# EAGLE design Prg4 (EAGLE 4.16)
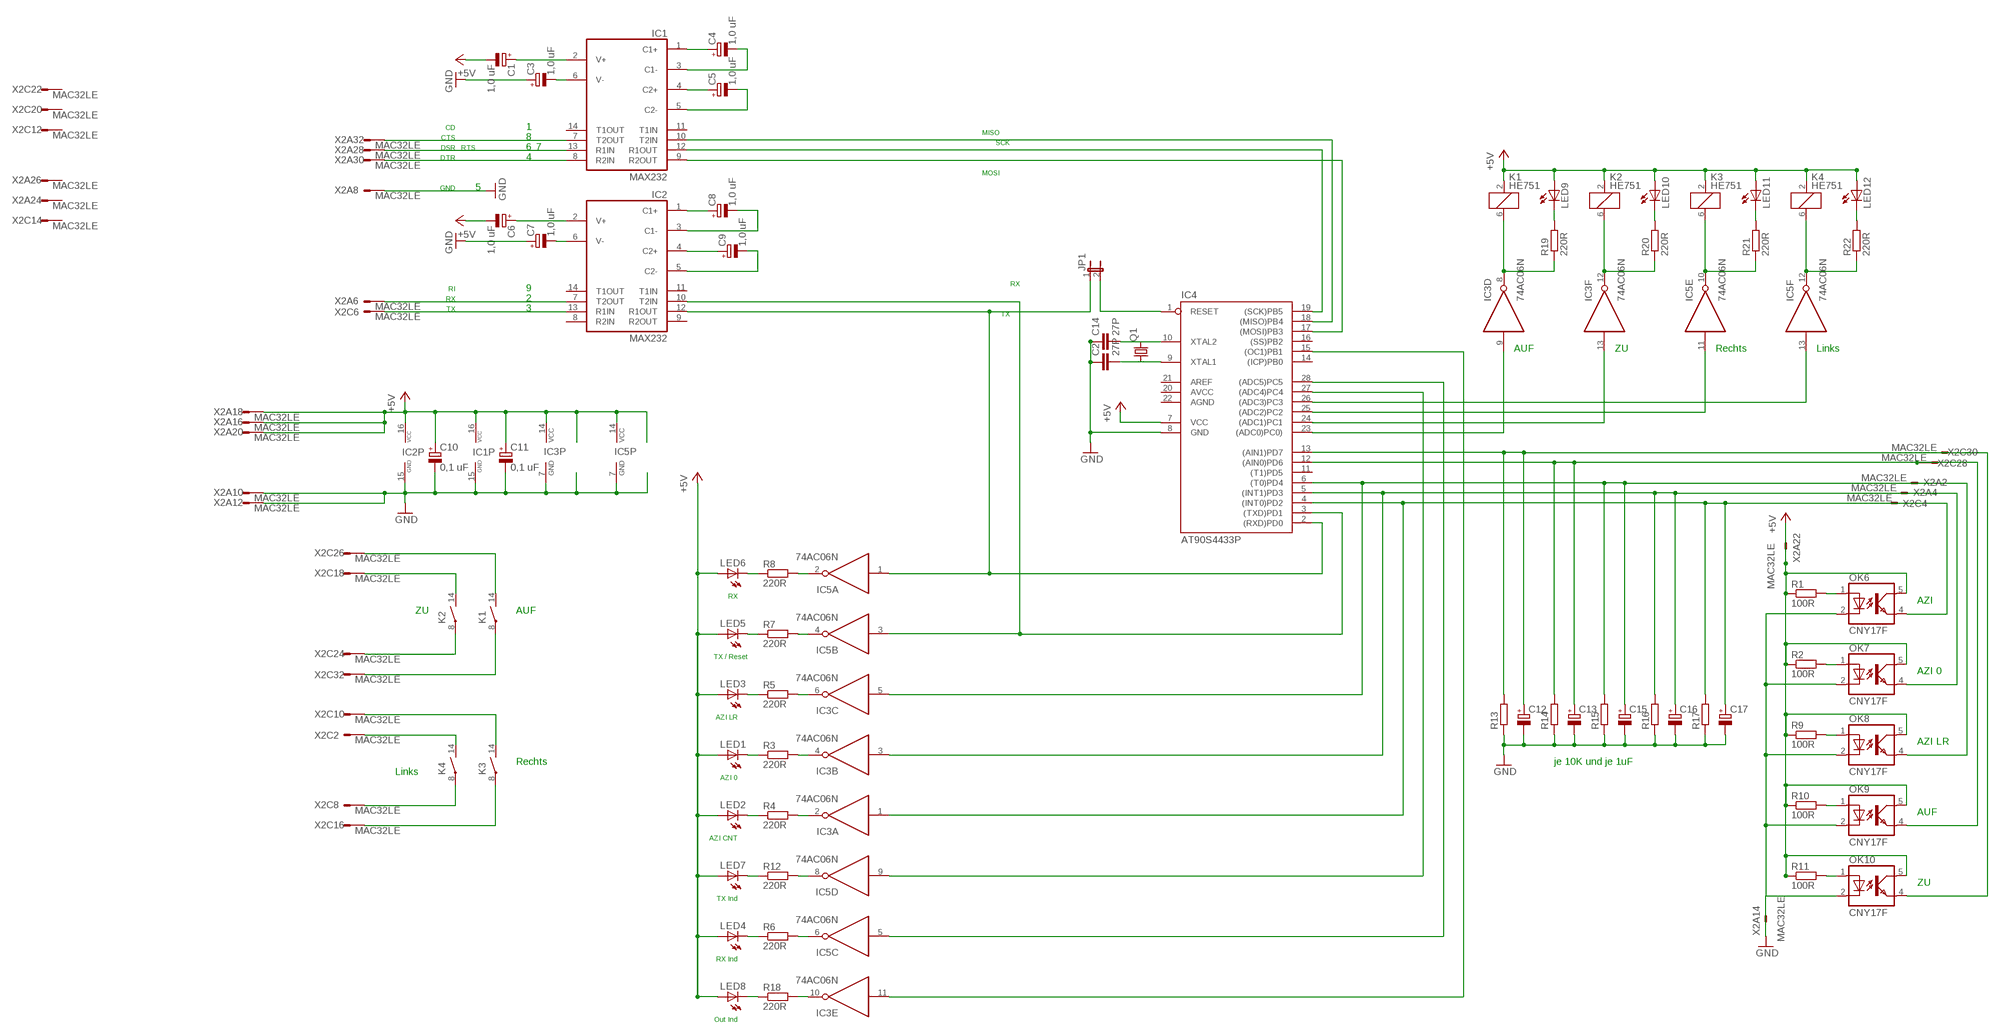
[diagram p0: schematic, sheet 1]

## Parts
C1  1,0 uF  CPOL-EUE2,5-6E  [E2,5-6E]
C2  27P  C-EU025-024X044  [C025-024X044]
C3  1,0 uF  CPOL-EUE2,5-6E  [E2,5-6E]
C4  1,0 uF  CPOL-EUE2,5-6E  [E2,5-6E]
C5  1,0 uF  CPOL-EUE2,5-6E  [E2,5-6E]
C6  1,0 uF  CPOL-EUE2,5-6E  [E2,5-6E]
C7  1,0 uF  CPOL-EUE2,5-6E  [E2,5-6E]
C8  1,0 uF  CPOL-EUE2,5-6E  [E2,5-6E]
C9  1,0 uF  CPOL-EUE2,5-6E  [E2,5-6E]
C10  0,1 uF  CPOL-EUE2,5-6E  [E2,5-6E]
C11  0,1 uF  CPOL-EUE2,5-6E  [E2,5-6E]
C12  CPOL-EUE2.5-4V  [E2,5RE]
C13  CPOL-EUE2.5-4V  [E2,5RE]
C14  27P  C-EU025-024X044  [C025-024X044]
C15  CPOL-EUE2.5-4V  [E2,5RE]
C16  CPOL-EUE2.5-4V  [E2,5RE]
C17  CPOL-EUE2.5-4V  [E2,5RE]
IC1  MAX232  [DIL16]
IC2  MAX232  [DIL16]
IC3  74AC06N  [DIL14]
IC4  AT90S4433P  [DIL28-3]
IC5  74AC06N  [DIL14]
JP1  JP1E  [JP1]
K1  HE751  [HE751]
K2  HE751  [HE751]
K3  HE751  [HE751]
K4  HE751  [HE751]
LED1  LED3MM  [LED3MM]
LED2  LED3MM  [LED3MM]
LED3  LED3MM  [LED3MM]
LED4  LED3MM  [LED3MM]
LED5  LED3MM  [LED3MM]
LED6  LED3MM  [LED3MM]
LED7  LED3MM  [LED3MM]
LED8  LED3MM  [LED3MM]
LED9  LED3MM  [LED3MM]
LED10  LED3MM  [LED3MM]
LED11  LED3MM  [LED3MM]
LED12  LED3MM  [LED3MM]
OK6  CNY17F  [DIL06]
OK7  CNY17F  [DIL06]
OK8  CNY17F  [DIL06]
OK9  CNY17F  [DIL06]
OK10  CNY17F  [DIL06]
Q1  CRYTALHC49S  [HC49/S]
R1  100R  R-EU_0204/7  [0204/7]
R2  100R  R-EU_0204/7  [0204/7]
R3  220R  R-EU_0207/2V  [0207/2V]
R4  220R  R-EU_0207/2V  [0207/2V]
R5  220R  R-EU_0207/2V  [0207/2V]
R6  220R  R-EU_0207/2V  [0207/2V]
R7  220R  R-EU_0207/2V  [0207/2V]
R8  220R  R-EU_0207/2V  [0207/2V]
R9  100R  R-EU_0204/7  [0204/7]
R10  100R  R-EU_0204/7  [0204/7]
R11  100R  R-EU_0204/7  [0204/7]
R12  220R  R-EU_0207/2V  [0207/2V]
R13  R-EU_0204/5  [0204/5]
R14  R-EU_0204/2V  [0204V]
R15  R-EU_0204/2V  [0204V]
R16  R-EU_0204V/3  [0204V/3]
R17  R-EU_0204/5  [0204/5]
R18  220R  R-EU_0207/2V  [0207/2V]
R19  220R  R-EU_0204V/3  [0204V/3]
R20  220R  R-EU_0207/2V  [0207/2V]
R21  220R  R-EU_0207/2V  [0207/2V]
R22  220R  R-EU_0207/2V  [0207/2V]
X2  MAC32LE  [MAC32L]

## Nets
+5V: C1.- C6.- C10.+ C11.+ IC1.16(VCC) IC2.16(VCC) IC3.14(P:VCC) IC4.7(VCC) IC5.14(P:VCC) K1.2 K2.2 K3.2 K4.2 LED1.A LED2.A LED3.A LED4.A LED5.A LED6.A LED7.A LED8.A LED9.A LED10.A LED11.A LED12.A OK6.5(COL) OK7.5(COL) OK8.5(COL) OK9.5(COL) OK10.5(COL) R1.1 R2.1 R9.1 R10.1 R11.1 X2.A16 X2.A18 X2.A20 X2.A22
GND: C2.1 C3.+ C7.+ C10.- C11.- C12.- C13.- C14.1 C15.- C16.- C17.- IC1.15(GND) IC2.15(GND) IC3.7(P:GND) IC4.8(GND) IC5.7(P:GND) OK6.2(C) OK7.2(C) OK8.2(C) OK9.2(C) OK10.2(C) R13.1 R14.1 R15.1 R16.1 R17.1 X2.A8 X2.A10 X2.A12 X2.A14
N$1: C4.+ IC1.1(C1+)
N$2: C4.- IC1.3(C1-)
N$3: C5.+ IC1.4(C2+)
N$4: C5.- IC1.5(C2-)
N$5: C3.- IC1.6(V-)
N$6: C1.+ IC1.2(V+)
N$7: C6.+ IC2.2(V+)
N$8: C7.- IC2.6(V-)
N$9: C8.+ IC2.1(C1+)
N$10: C9.+ IC2.4(C2+)
N$11: C9.- IC2.5(C2-)
N$12: C8.- IC2.3(C1-)
N$13: K2.14(2:S) X2.C18
N$14: K4.8(2:P) X2.C8
N$15: K3.14(2:S) X2.C10
N$16: K4.14(2:S) X2.C2
N$17: IC1.13(R1IN) X2.A28
N$18: IC1.8(R2IN) X2.A30
N$19: IC2.7(T2OUT) X2.A6
N$20: IC1.9(R2OUT) IC4.17((MOSI)PB3)
N$21: IC3.8(D:O) K1.6 R19.1
N$22: IC3.12(F:O) K2.6 R20.1
N$23: IC2.12(R1OUT) IC4.2((RXD)PD0) IC5.1(A:I) JP1.1
N$24: IC2.10(T2IN) IC4.3((TXD)PD1) IC5.3(B:I)
N$25: LED1.K(C) R3.1
N$26: IC3.4(B:O) R3.2
N$27: LED2.K(C) R4.1
N$28: IC3.2(A:O) R4.2
N$29: LED3.K(C) R5.1
N$30: IC3.6(C:O) R5.2
N$31: LED4.K(C) R6.1
N$32: IC5.6(C:O) R6.2
N$33: LED5.K(C) R7.1
N$34: IC5.4(B:O) R7.2
N$35: C14.2 IC4.10(XTAL2) Q1.2
N$36: C2.2 IC4.9(XTAL1) Q1.1
N$37: IC3.9(D:I) IC4.23((ADC0)PC0))
N$38: IC5.12(F:O) K4.6 R22.1
N$39: IC4.26((ADC3)PC3) IC5.13(F:I)
N$40: IC5.10(E:O) K3.6 R21.1
N$41: IC1.10(T2IN) IC4.18((MISO)PB4)
N$42: IC4.1(RESET) JP1.2
N$43: IC5.2(A:O) R8.2
N$44: IC5.8(D:O) R12.2
N$45: LED6.K(C) R8.1
N$46: LED7.K(C) R12.1
N$47: IC4.27((ADC4)PC4) IC5.9(D:I)
N$48: IC4.28((ADC5)PC5) IC5.5(C:I)
N$49: IC1.12(R1OUT) IC4.19((SCK)PB5)
N$50: IC3.13(F:I) IC4.24((ADC1)PC1)
N$51: IC4.25((ADC2)PC2) IC5.11(E:I)
N$52: OK6.1(A) R1.2
N$53: OK7.1(A) R2.2
N$54: OK8.1(A) R9.2
N$55: OK9.1(A) R10.2
N$56: OK10.1(A) R11.2
N$57: IC1.7(T2OUT) X2.A32
N$58: C16.+ IC3.3(B:I) IC4.5((INT1)PD3) OK7.4(EMIT) R16.2 X2.A4
N$59: IC3.10(E:O) R18.2
N$60: C15.+ IC3.5(C:I) IC4.6((T0)PD4) OK8.4(EMIT) R15.2 X2.A2
N$61: C13.+ IC4.12((AIN0)PD6) OK9.4(EMIT) R14.2 X2.C28
N$62: K1.14(2:S) X2.C26
N$63: C12.+ IC4.13((AIN1)PD7) OK10.4(EMIT) R13.2 X2.C30
N$64: K2.8(2:P) X2.C24
N$65: C17.+ IC3.1(A:I) IC4.4((INT0)PD2) OK6.4(EMIT) R17.2 X2.C4
N$66: IC2.13(R1IN) X2.C6
N$67: LED8.K(C) R18.1
N$68: IC3.11(E:I) IC4.15((OC1)PB1)
N$69: LED9.K(C) R19.2
N$70: LED10.K(C) R20.2
N$71: K1.8(2:P) X2.C32
N$72: K3.8(2:P) X2.C16
N$73: LED11.K(C) R21.2
N$74: LED12.K(C) R22.2
Unconnected: IC1.11(T1IN) IC1.14(T1OUT) IC2.8(R2IN) IC2.9(R2OUT) IC2.11(T1IN) IC2.14(T1OUT) IC4.11((T1)PD5) IC4.14((ICP)PB0) IC4.16((SS)PB2) X2.A24 X2.A26 X2.C12 X2.C14 X2.C20 X2.C22

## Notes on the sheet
- CD | 1 | MISO
- CTS | 8 | SCK
- DSR | RTS | 6 | 7
- DTR | 4
- MOSI
- GND | 5
- RX
- RI | 9
- RX | 2
- TX | 3 | TX
- AUF | ZU | Rechts | Links
- RX
- AZI
- ZU | AUF
- TX / Reset
- AZI 0
- AZI LR
- AZI LR
- Rechts | je 10K und je 1uF
- Links | AZI 0
- AUF
- AZI CNT
- ZU
- TX Ind
- RX Ind
- Out Ind

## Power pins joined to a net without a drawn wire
AGND: IC4.22(AGND)
AREF: IC4.21(AREF)
AVCC: IC4.20(AVCC)

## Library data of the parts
C1 C3-C13 C15-C17 = rcl:CPOL-EU: POLARIZED CAPACITOR, European symbol
C2 C14 = rcl:C-EU: CAPACITOR, European symbol
IC1 IC2 = maxim:MAX232: RS232 TRANSEIVER
IC3 IC5 = 74xx-eu:74*06: Hex INVERTER, open collector high-voltage output
IC4 = atmel:AT90S4433: MICROCONTROLLER 4 Kbytes FLASH 128 bytes SRAM 256 bytes EEPROM UART 6-channel 10 bit ADC
JP1 = jumper:JP1E: JUMPER
K1-K4 = relay:HE751: RELAY reed, 1 x norm. open, Hamlin
LED1-LED12 = led:LED: LED
OK6-OK10 = optocoupler:CNY17F: SIEMENS OPTO COUPLER
Q1 = crystal:CRYTAL: CRYSTAL
R1-R22 = rcl:R-EU_: RESISTOR, European symbol
X2 = con-vg:MAC32LE: CONNECTOR male, 32 pins, single, type D, rows AC, grid 5.08 mm with mounting clip

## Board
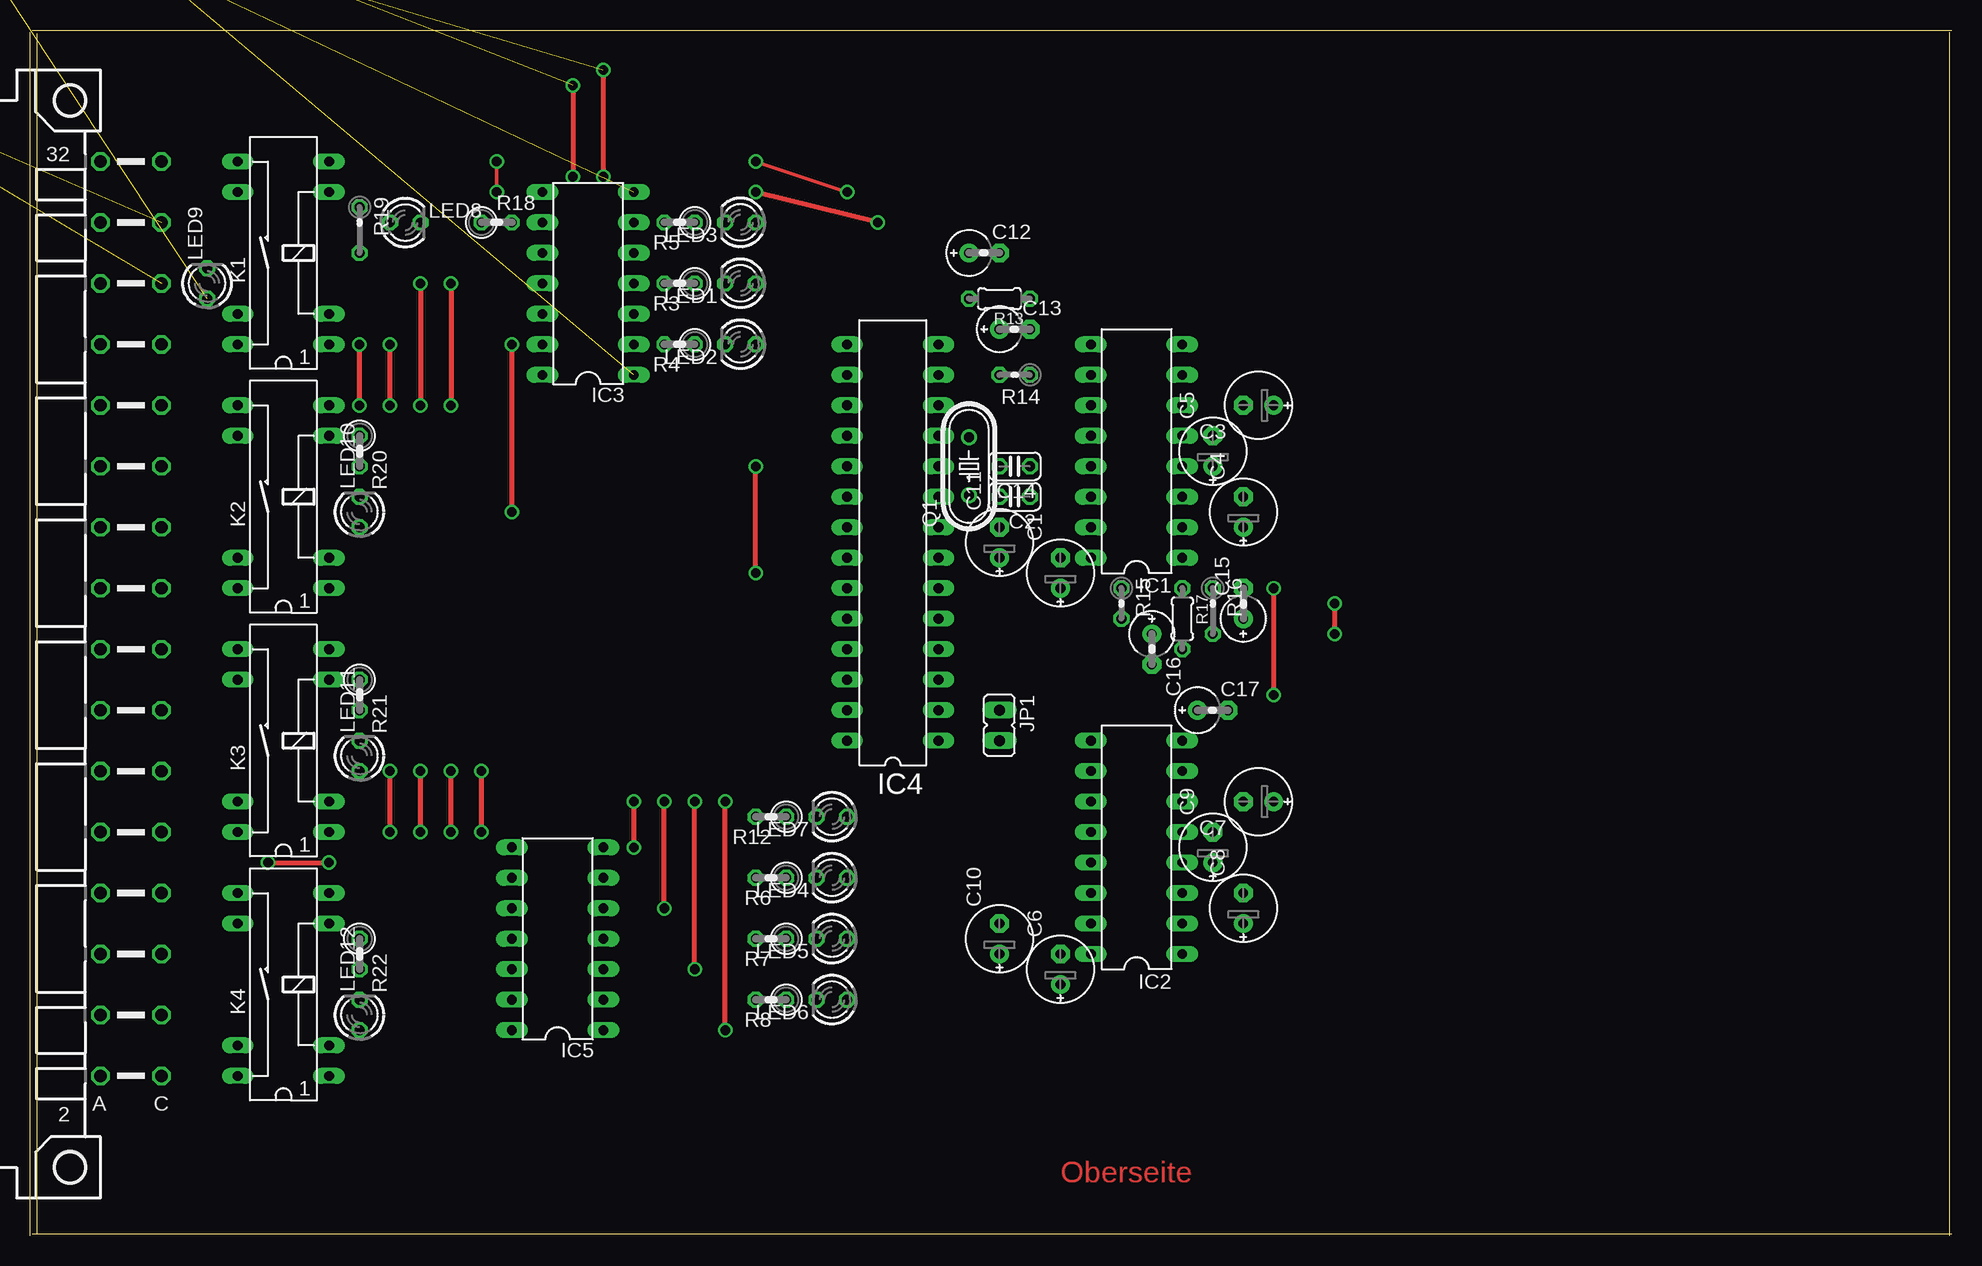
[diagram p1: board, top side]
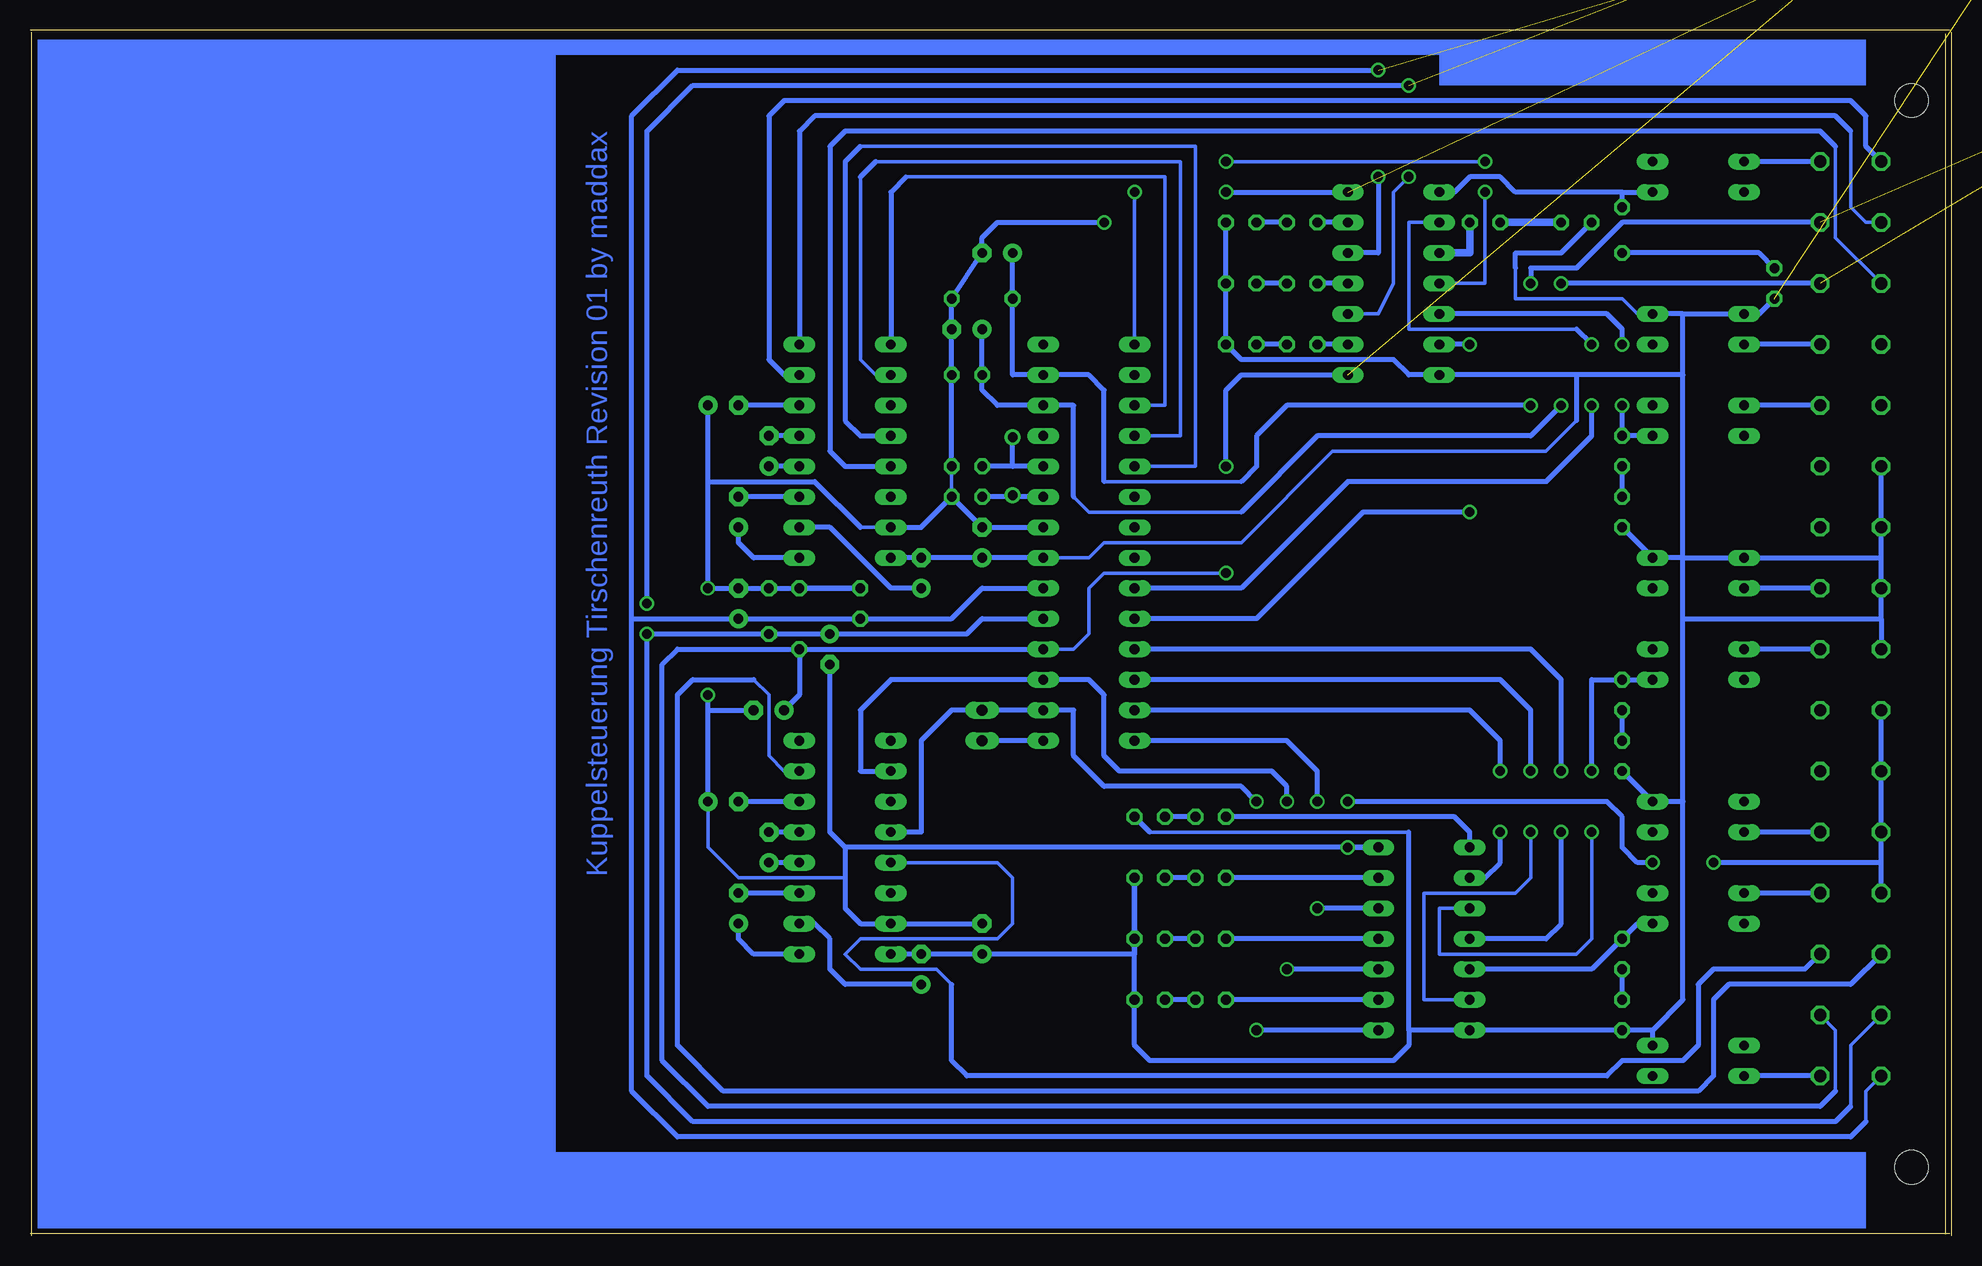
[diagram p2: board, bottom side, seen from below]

Size 160.18 x 100.49 mm. Coordinates in mm from the lower left corner, seen from the top.
Outline: 160.02,0 160.02,100.32
Outline: 80.18,100.49 160.18,100.49
Outline: 0.17,100.49 80.17,100.49
Outline: 0,0 0,100.32
Outline: 0.17,0.16 80.17,0.16
Outline: 80.18,0.16 160.18,0.16
Copper layers (1*16): Top 0.035mm / dielectric 1.5mm / Bottom 0.035mm
Design rules "default": minimum track width 10mil, minimum drill 24mil, track to track 8mil, track to pad 8mil, pad to pad 8mil, via to via 8mil, smd to smd 8mil, copper to edge 40mil, drill to drill 8mil, minimum pad ring 10mil, minimum via ring 8mil, stop-mask expansion 4mil, vias tented up to drill 0mil, thermal gap 10mil

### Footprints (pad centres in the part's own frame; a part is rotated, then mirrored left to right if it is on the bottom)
E2,5-6E = drill 0.813 pad 1.575 round: + -1.27,0 | drill 0.813 pad 1.575 octagon: - 1.27,0
C025-024X044 = drill 0.813 octagon: 1 -1.27,0; 2 1.27,0
E2,5RE = drill 0.813 pad 1.575 round: + -1.27,0 | drill 0.813 pad 1.575 octagon: - 1.27,0
DIL16 = drill 0.813 long: 1 -8.89,-3.81; 2 -6.35,-3.81; 3 -3.81,-3.81; 4 -1.27,-3.81; 5 1.27,-3.81; 6 3.81,-3.81; 7 6.35,-3.81; 8 8.89,-3.81; 9 8.89,3.81; 10 6.35,3.81; 11 3.81,3.81; 12 1.27,3.81; 13 -1.27,3.81; 14 -3.81,3.81; 15 -6.35,3.81; 16 -8.89,3.81
DIL14 = drill 0.813 long: 1 -7.62,-3.81; 2 -5.08,-3.81; 3 -2.54,-3.81; 4 0,-3.81; 5 2.54,-3.81; 6 5.08,-3.81; 7 7.62,-3.81; 8 7.62,3.81; 9 5.08,3.81; 10 2.54,3.81; 11 0,3.81; 12 -2.54,3.81; 13 -5.08,3.81; 14 -7.62,3.81
DIL28-3 = drill 0.813 long: 1 -16.51,-3.81; 2 -13.97,-3.81; 3 -11.43,-3.81; 4 -8.89,-3.81; 5 -6.35,-3.81; 6 -3.81,-3.81; 7 -1.27,-3.81; 8 1.27,-3.81; 9 3.81,-3.81; 10 6.35,-3.81; 11 8.89,-3.81; 12 11.43,-3.81; 13 13.97,-3.81; 14 16.51,-3.81; 15 16.51,3.81; 16 13.97,3.81; 17 11.43,3.81; 18 8.89,3.81; 19 6.35,3.81; 20 3.81,3.81; 21 1.27,3.81; 22 -1.27,3.81; 23 -3.81,3.81; 24 -6.35,3.81; 25 -8.89,3.81; 26 -11.43,3.81; 27 -13.97,3.81; 28 -16.51,3.81
JP1 = drill 0.914 long: 1 0,-1.27; 2 0,1.27
HE751 = drill 0.813 long: 1 -7.62,-3.81; 2 -5.08,-3.81; 6 5.08,-3.81; 7 7.62,-3.81; 8 7.62,3.81; 9 5.08,3.81; 13 -5.08,3.81; 14 -7.62,3.81
LED3MM = drill 0.813 octagon: A -1.27,0; K 1.27,0
DIL06 = drill 0.813 long: 1 -2.54,-3.81; 2 0,-3.81; 3 2.54,-3.81; 4 2.54,3.81; 5 0,3.81; 6 -2.54,3.81
HC49/S = drill 0.813 round: 1 -2.413,0; 2 2.413,0
0204/7 = drill 0.813 octagon: 1 -3.81,0; 2 3.81,0
0207/2V = drill 0.813 octagon: 1 -1.27,0; 2 1.27,0
0204/5 = drill 0.813 octagon: 1 -2.54,0; 2 2.54,0
0204V = drill 0.813 octagon: 1 -1.27,0; 2 1.27,0
0204V/3 = drill 0.813 octagon: 1 -1.27,0; 2 2.54,0
MAC32L = drill 1.016 octagon: A2 -2.54,36.83; A4 -2.54,31.75; A6 -2.54,26.67; A8 -2.54,21.59; A10 -2.54,16.51; A12 -2.54,11.43; A14 -2.54,6.35; A16 -2.54,1.27; A18 -2.54,-3.81; A20 -2.54,-8.89; A22 -2.54,-13.97; A24 -2.54,-19.05; A26 -2.54,-24.13; A28 -2.54,-29.21; A30 -2.54,-34.29; A32 -2.54,-39.37; C2 -7.62,36.83; C4 -7.62,31.75; C6 -7.62,26.67; C8 -7.62,21.59; C10 -7.62,16.51; C12 -7.62,11.43; C14 -7.62,6.35; C16 -7.62,1.27; C18 -7.62,-3.81; C20 -7.62,-8.89; C22 -7.62,-13.97; C24 -7.62,-19.05; C26 -7.62,-24.13; C28 -7.62,-29.21; C30 -7.62,-34.29; C32 -7.62,-39.37 | hole 2.794: 0,44.45; 0,-44.45

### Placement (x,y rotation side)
C1  85.89,55.24 90 top
C2  82.08,61.59 180 top
C3  102.4,69.21 180 top
C4  101.13,60.32 90 top
C5  98.59,65.4 90 top
C6  85.89,22.22 90 top
C7  102.4,36.19 180 top
C8  101.13,27.3 90 top
C9  98.59,32.38 90 top
C10  80.81,24.76 90 top
C11  80.81,57.78 90 top
C12  79.54,81.91 0 top
C13  82.08,75.56 0 top
C14  82.08,64.13 180 top
C15  101.13,52.7 90 top
C16  93.51,48.89 270 top
C17  98.59,43.81 0 top
IC1  92.24,65.4 90 top
IC2  92.24,32.38 90 top
IC3  46.52,79.37 90 top
IC4  71.92,57.78 90 top
IC5  43.98,24.76 90 top
JP1  80.81,42.54 180 top
K1  21.12,81.91 90 top
K2  21.12,61.59 90 top
K3  21.12,41.27 90 top
K4  21.12,20.95 90 top
LED1  59.22,79.37 180 top
LED2  59.22,74.29 180 top
LED3  59.22,84.45 180 top
LED4  66.84,29.84 180 top
LED5  66.84,24.76 180 top
LED6  66.84,19.68 180 top
LED7  66.84,34.92 180 top
LED8  31.28,84.45 0 top
LED9  14.77,79.37 90 top
LED10  27.47,60.32 90 top
LED11  27.47,40 90 top
LED12  27.47,18.41 90 top
OK6  not placed on the board
OK7  not placed on the board
OK8  not placed on the board
OK9  not placed on the board
OK10  not placed on the board
Q1  78.27,64.13 90 top
R1  not placed on the board
R2  not placed on the board
R3  54.14,79.37 180 top
R4  54.14,74.29 180 top
R5  54.14,84.45 180 top
R6  61.76,29.84 180 top
R7  61.76,24.76 180 top
R8  61.76,19.68 180 top
R9  not placed on the board
R10  not placed on the board
R11  not placed on the board
R12  61.76,34.92 180 top
R13  80.81,78.1 180 top
R14  82.08,71.75 180 top
R15  90.97,52.7 270 top
R16  98.59,52.7 270 top
R17  96.05,51.43 270 top
R18  38.9,84.45 0 top
R19  27.47,84.45 270 top
R20  27.47,65.4 270 top
R21  27.47,45.08 270 top
R22  27.47,23.49 270 top
X2  3.34,50.16 180 top

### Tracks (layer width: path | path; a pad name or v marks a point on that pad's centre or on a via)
+5V  (10 unrouted)
  Bottom 0.305: IC4.7 71.92,56.51 70.65,57.78 59.22,57.78 51.6,65.4 33.82,65.4 31.28,67.94 | 45.25,33.65 66.84,33.65 | K1.2 26.2,76.83 27.47,78.1 36.36,78.1 36.36,80.64
  Bottom 0.406: C10.+ C6.- | C6.- IC2.16 | C10.+ C6.- | IC4.7 C11.+ C1.- IC1.16 | 22.39,36.19 K3.2 LED11.A | 66.84,33.65 LED7.A | LED4.A 68.11,28.57 | 68.11,23.49 LED5.A | 45.25,17.14 45.25,33.65 | 45.25,17.14 IC5.14 LED12.A 24.93,17.14 | 45.25,17.14 45.25,15.87 46.52,14.6 66.84,14.6 68.11,15.87 LED6.A LED4.A | 68.11,23.49 C10.+ | K4.2 24.93,17.14 | 24.93,17.14 22.39,19.68 22.39,36.19 | 22.39,51.43 22.39,56.51 | 22.39,56.51 K2.2 LED10.A | 22.39,56.51 22.39,71.75 | 22.39,71.75 22.39,76.83 | 22.39,76.83 K1.2 | 22.39,71.75 31.28,71.75 | 31.28,71.75 IC3.14 45.25,71.75 46.52,73.02 59.22,73.02 LED2.A LED1.A LED3.A | 5.88,51.43 X2.A18 5.88,56.51 | 22.39,51.43 5.88,51.43 | 22.39,36.19 22.39,51.43 | 5.88,51.43 X2.A16 | 31.28,71.75 31.28,67.94 | 22.39,56.51 22.39,76.83 | 22.39,56.51 5.88,56.51 | 5.88,56.51 X2.A20 X2.A22 | LED4.A 68.11,23.49 | 36.36,80.64 36.36,81.91 32.55,81.91 LED8.A | 22.39,76.83 16.04,76.83 LED9.A
GND  (via drill 0.8)  (5 unrouted)
  Top 0.406: v70.65,84.45 v60.49,86.99 | v50.33,36.19 v50.33,32.38 | v19.85,31.11 v24.93,31.11 | v103.67,45.08 v103.67,53.97 v103.67,45.08
  Bottom 0.305: C7.+ 103.67,32.38 101.13,29.84 92.24,29.84 | 90.97,59.05 IC1.15 | C2.1 C14.1
  Bottom 0.406: IC4.8 C11.- C2.1 85.89,59.05 IC1.15 | 90.97,59.05 94.78,62.86 103.67,62.86 | IC2.15 C10.- IC2.15 | 103.67,62.86 C3.+ | R16.1 R15.1 | v103.67,53.97 C15.- | C15.- R16.1 | R16.1 R15.1 | R15.1 R17.1 R16.1 | IC2.15 90.97,26.03 92.24,27.3 92.24,29.84 92.24,32.38 | 92.24,32.38 IC5.7 v50.33,32.38 | v103.67,53.97 C15.- | C15.- R16.1 | R16.1 R15.1 | R16.1 R15.1 | C7.+ 103.67,43.81 | 103.67,43.81 v103.67,45.08 | v103.67,53.97 C15.- | C15.- R16.1 | v103.67,53.97 103.67,62.86 | 103.67,43.81 C17.- | 92.24,32.38 93.51,33.65 C16.- | C15.- R16.1 | v60.49,86.99 IC3.7 | v50.33,36.19 28.74,36.19 27.47,34.92 27.47,32.38 26.2,31.11 v24.93,31.11 | X2.A8 5.88,31.11 | 5.88,31.11 v19.85,31.11 | C14.1 R14.1 C13.- R13.1 C12.- 80.81,83.18 79.54,84.45 v70.65,84.45 | 5.88,31.11 X2.A10 X2.A12 X2.A14
N$1
  Bottom 0.406: C4.+ 101.13,57.78 99.86,56.51 IC1.1
N$2
  Bottom 0.406: IC1.3 C4.-
N$3
  Bottom 0.406: IC1.4 C5.+
N$4
  Bottom 0.406: IC1.5 C5.-
N$5
  Bottom 0.406: IC1.6 C3.-
N$6
  Bottom 0.406: C1.+ 88.43,53.97 93.51,59.05 IC1.2
N$7
  Bottom 0.406: C6.+ 92.24,20.95 93.51,22.22 93.51,24.76 94.78,26.03 IC2.2
N$8
  Bottom 0.406: IC2.6 C7.-
N$9
  Bottom 0.406: IC2.1 99.86,23.49 101.13,24.76 C8.+
N$10
  Bottom 0.406: IC2.4 C9.+
N$11
  Bottom 0.406: IC2.5 C9.-
N$12
  Bottom 0.406: IC2.3 C8.-
N$13
  Bottom 0.406: X2.C18 K2.14
N$14
  Bottom 0.406: X2.C8 K4.8
N$15
  Bottom 0.406: X2.C10 K3.14
N$16
  Bottom 0.406: X2.C2 K4.14
N$17
  Bottom 0.305: 9.69,90.8 9.69,83.18 X2.A28
  Bottom 0.406: IC1.13 92.24,64.13 93.51,65.4 93.51,90.8 92.24,92.07 10.96,92.07 9.69,90.8
N$18
  Bottom 0.305: 8.42,92.07 8.42,85.72 7.15,84.45 X2.A30
  Bottom 0.406: IC1.8 96.05,92.07 94.78,93.34 9.69,93.34 8.42,92.07
N$19
  Bottom 0.305: 99.86,46.35 98.59,45.08 98.59,40 97.32,38.73 IC2.7
  Bottom 0.406: 99.86,46.35 104.94,46.35 106.21,45.08 106.21,15.87 102.4,12.06 21.12,12.06 19.85,13.33 19.85,19.68 18.58,20.95 8.42,20.95 X2.A6
N$20
  Bottom 0.305: 87.16,88.26 65.57,88.26 65.57,69.21 IC4.17
  Bottom 0.406: IC1.9 88.43,86.99 87.16,88.26
N$21
  Bottom 0.406: 27.47,86.99 K1.6 | 27.47,86.99 36.36,86.99 37.63,88.26 40.17,88.26 41.44,86.99 IC3.8 | R19.1 27.47,86.99
N$22  (via drill 0.8)
  Top 0.406: v27.47,69.21 v27.47,74.29
  Bottom 0.406: K2.6 R20.1 v27.47,69.21 | v27.47,74.29 27.47,75.56 28.74,76.83 IC3.12
N$23  (via drill 0.8)
  Top 0.406: v57.95,17.14 v57.95,36.19
  Bottom 0.406: IC5.1 v57.95,17.14 | v57.95,36.19 59.22,37.46 70.65,37.46 73.19,40 73.19,43.81 IC4.2 JP1.1 83.35,43.81 85.89,41.27 85.89,33.65 IC2.12
N$24  (via drill 0.8)
  Top 0.406: v55.41,22.22 v55.41,36.19
  Bottom 0.406: IC5.3 v55.41,22.22 | v55.41,36.19 55.41,37.46 56.68,38.73 69.38,38.73 70.65,40 70.65,45.08 71.92,46.35 IC4.3 88.43,46.35 90.97,43.81 90.97,38.73 IC2.10
N$25
  Bottom 0.406: R3.1 LED1.K
N$26
  Bottom 0.406: IC3.4 R3.2
N$27
  Bottom 0.406: R4.1 LED2.K
N$28
  Bottom 0.406: IC3.2 R4.2
N$29
  Bottom 0.406: R5.1 LED3.K
N$30
  Bottom 0.406: IC3.6 R5.2
N$31
  Bottom 0.406: R6.1 LED4.K
N$32
  Bottom 0.406: IC5.6 R6.2
N$33
  Bottom 0.406: R7.1 LED5.K
N$34
  Bottom 0.406: IC5.4 R7.2
N$35
  Bottom 0.406: IC4.10 78.27,64.13 | 78.27,64.13 C14.2 | 78.27,66.67 Q1.2 78.27,64.13
N$36
  Bottom 0.406: 78.27,61.59 C2.2 | 78.27,61.59 Q1.1 | IC4.9 78.27,61.59
N$37  (via drill 0.8)
  Top 0.406: v30.01,69.21 v30.01,74.29
  Bottom 0.305: 31.28,75.56 45.25,75.56 45.25,84.45 IC3.9
  Bottom 0.406: v30.01,69.21 30.01,66.67 33.82,62.86 50.33,62.86 59.22,53.97 IC4.23 | v30.01,74.29 31.28,75.56
N$38
  Bottom 0.406: K4.6 26.2,26.03 R22.1 30.01,22.22 IC5.12
N$39  (via drill 0.8)
  Top 0.406: v35.09,33.65 v35.09,38.73
  Bottom 0.305: v35.09,33.65 35.09,29.84 36.36,28.57 43.98,28.57 43.98,19.68 IC5.13
  Bottom 0.406: v35.09,38.73 35.09,43.81 37.63,46.35 IC4.26
N$40  (via drill 0.8)
  Top 0.406: v30.01,33.65 v30.01,38.73
  Bottom 0.305: v30.01,33.65 30.01,24.76 31.28,23.49 42.71,23.49 42.71,27.3 IC5.10
  Bottom 0.406: v30.01,38.73 30.01,46.35 R21.1 | R21.1 K3.6 R21.1
N$41
  Bottom 0.305: IC1.10 89.7,71.75 90.97,73.02 90.97,88.26 | 89.7,89.53 64.3,89.53 64.3,66.67 IC4.18
  Bottom 0.406: 89.7,89.53 90.97,88.26
N$42
  Bottom 0.406: IC4.1 JP1.2
N$43
  Bottom 0.406: IC5.2 R8.2
N$44
  Bottom 0.406: R12.2 41.44,34.92 40.17,33.65 IC5.8
N$45
  Bottom 0.406: R8.1 LED6.K
N$46
  Bottom 0.406: R12.1 LED7.K
N$47  (via drill 0.8)
  Top 0.406: v37.63,33.65 v37.63,38.73
  Bottom 0.406: v37.63,38.73 37.63,41.27 40.17,43.81 IC4.27 | v37.63,33.65 37.63,31.11 38.9,29.84 IC5.9
N$48  (via drill 0.8)
  Top 0.406: v52.87,27.3 v52.87,36.19
  Bottom 0.406: v52.87,36.19 52.87,38.73 55.41,41.27 IC4.28 | IC5.5 v52.87,27.3
N$49
  Bottom 0.305: 90.97,90.8 63.03,90.8 63.03,64.13 IC4.19
  Bottom 0.406: IC1.12 90.97,66.67 92.24,67.94 92.24,89.53 90.97,90.8
N$50  (via drill 0.8)
  Top 0.406: v40.17,60.32 v40.17,74.29
  Bottom 0.406: v40.17,60.32 49.06,60.32 57.95,51.43 IC4.24 | v40.17,74.29 IC3.13
N$51  (via drill 0.8)
  Top 0.406: v32.55,33.65 v32.55,38.73
  Bottom 0.406: v32.55,38.73 32.55,46.35 35.09,48.89 IC4.25 | v32.55,33.65 32.55,26.03 33.82,24.76 IC5.11
N$52  (1 unrouted)
N$53  (1 unrouted)
N$54  (1 unrouted)
N$55  (1 unrouted)
N$56  (1 unrouted)
N$57
  Bottom 0.406: IC1.7 97.32,71.75 98.59,73.02 98.59,93.34 97.32,94.61 8.42,94.61 7.15,93.34 7.15,90.8 X2.A32
N$58  (via drill 0.8)  (1 unrouted)
  Top 0.406: v45.25,95.88 v45.25,88.26 | v108.75,50.16 v108.75,52.7
  Bottom 0.305: 8.42,10.79 8.42,15.87 X2.A4 | IC3.3 47.79,76.83 46.52,79.37 46.52,86.99 v45.25,88.26
  Bottom 0.406: R16.2 C16.+ | C16.+ 82.08,50.16 80.81,51.43 IC4.5 | R16.2 v108.75,50.16 108.75,13.33 104.94,9.52 9.69,9.52 8.42,10.79 | R16.2 C16.+ | v45.25,95.88 104.94,95.88 108.75,92.07 v108.75,52.7
N$59
  Bottom 0.61: R18.2 40.17,81.91 IC3.10
N$60  (via drill 0.8)  (1 unrouted)
  Top 0.406: v47.79,97.15 v47.79,88.26
  Bottom 0.305: 7.15,9.52 7.15,12.06 X2.A2
  Bottom 0.406: IC4.6 80.81,53.97 83.35,51.43 R15.2 C15.+ 110.02,51.43 | 110.02,51.43 110.02,12.06 106.21,8.25 8.42,8.25 7.15,9.52 | IC3.5 47.79,81.91 v47.79,88.26 | v47.79,97.15 106.21,97.15 110.02,93.34 110.02,51.43
N$61  (via drill 0.8)  (1 unrouted)
  Top 0.406: v32.55,79.37 v32.55,69.21
  Bottom 0.305: 59.22,60.32 71.92,60.32 73.19,61.59
  Bottom 0.406: C13.+ R14.2 80.81,70.48 79.54,69.21 IC4.12 73.19,69.21 73.19,61.59 | v32.55,69.21 35.09,66.67 52.87,66.67 59.22,60.32 | X2.C28 v32.55,79.37
N$62
  Bottom 0.406: X2.C26 K1.14
N$63  (via drill 0.8)  (1 unrouted)
  Top 0.406: v35.09,79.37 v35.09,69.21
  Bottom 0.305: 59.22,62.86 70.65,62.86
  Bottom 0.406: C12.+ R13.2 78.27,71.75 IC4.13 71.92,71.75 70.65,70.48 70.65,62.86 | X2.C30 27.47,84.45 31.28,80.64 35.09,80.64 v35.09,79.37 | v35.09,69.21 55.41,69.21 57.95,66.67 57.95,64.13 59.22,62.86
N$64
  Bottom 0.406: X2.C24 K2.8
N$65  (via drill 0.8)  (1 unrouted)
  Top 0.406: v60.49,55.24 v60.49,64.13
  Bottom 0.305: 9.69,12.06 9.69,17.14 X2.C4 | IC4.4 73.19,48.89 71.92,50.16 71.92,53.97 70.65,55.24 v60.49,55.24
  Bottom 0.406: R17.2 IC4.4 | R17.2 106.21,48.89 107.48,47.62 107.48,14.6 103.67,10.79 10.96,10.79 9.69,12.06 | C17.+ 96.05,45.08 R17.2 | v60.49,64.13 60.49,70.48 59.22,71.75 IC3.1
N$66
  Bottom 0.305: 83.35,20.95 84.62,22.22 90.97,22.22 92.24,23.49 90.97,24.76 79.54,24.76 78.27,26.03 78.27,29.84 79.54,31.11 IC2.13
  Bottom 0.406: X2.C6 12.23,22.22 19.85,22.22 21.12,20.95 21.12,15.87 22.39,14.6 27.47,14.6 28.74,13.33 82.08,13.33 83.35,14.6 83.35,20.95
N$67
  Bottom 0.61: LED8.K R18.1
N$68  (via drill 0.8)
  Top 0.305: v38.9,86.99 v38.9,89.53 | v60.49,89.53 v68.11,86.99
  Bottom 0.305: IC3.11 38.9,79.37 v38.9,86.99 | v38.9,89.53 v60.49,89.53 | v68.11,86.99 IC4.15
N$69
  Bottom 0.406: R19.2 16.04,81.91 LED9.K
N$70
  Bottom 0.406: LED10.K R20.2
N$71
  Bottom 0.406: X2.C32 K1.8
N$72
  Bottom 0.406: X2.C16 K3.8
N$73
  Bottom 0.406: LED11.K R21.2
N$74
  Bottom 0.406: LED12.K R22.2
(copper drawn outside any net)
  shapes: Bottom area x4

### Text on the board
Top: Oberseite
Bottom: Kuppelsteuerung Tirschenreuth Revision 01 by maddax
Drill_legend: Bohrlegende | Datum: 15.11.2006 21:04:55 | 4 unterschiedliche Durchmesser | mit Standardsymbol! (48 Bohrungen) | 2.7940 mm / 110.000 mil | 0.9144 mm / 36.000 mil | 0.8000 mm / 31.496 mil | 0.6000 mm / 23.622 mil | 1.0160 mm / 40.000 mil | 0.8128 mm / 32.000 mil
